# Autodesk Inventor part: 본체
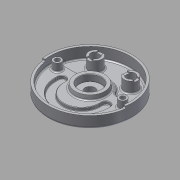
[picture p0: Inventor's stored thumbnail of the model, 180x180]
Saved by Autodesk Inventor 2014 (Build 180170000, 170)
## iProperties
Created: 2015-06
Part Number: 본체
Material: 알루미늄 6061
Document SubType Name: Modeling
Designer: MYHOME
Mass: 1071.05 g
Surface Area: 1034.6 cm^2
Volume: 395.223 cm^3
Density: 2.71 g/cm^3
Appearance: 알루미늄 - 평지
Author: MYHOME
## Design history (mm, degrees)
sketch "스케치1"
  geometry: C1 r 95 at (0, 0); C2 r 90 at (0, 0); 1 further point
  constraints: 2 centre point, 2 coincident
  dimensions: "d0" = 190 diameter of C1; "d1" = 180 diameter of C2
extrude "돌출1" new body sketch "스케치1" distance "d2" = 32; taper "d3" = 0 deg
extrude "돌출2" join sketch "스케치1" distance "d4" = 7; taper "d5" = 0 deg
sketch "스케치3"
  geometry: L1 (-88.566, 16)-(88.566, 16); A1 r 90 centre (0, 0) between (88.566, 16) and (-88.566, 16) reference; A2 r 42 centre (0, 0) between (-38.833, 16) and (38.833, 16)
  constraints: 4 point on circle, 2 end point, 2 point on line, 1 centre point, 1 coincident, 1 horizontal
  dimensions: "d11" = 16 distance from line of A1.centre L1; "d12" = 84 diameter of A2
extrude "돌출4" join sketch "스케치3" distance "d13" = 7; taper "d14" = 0 deg
fillet "모깎기2" dims "d15" = 10
sketch "스케치4"
  geometry: C1 r 15 at (-40, 52); C2 r 15 at (40, 52); A1 r 90 centre (0, 0) between (85.114, 29.25) and (-85.114, 29.25) reference
  constraints: 2 centre point, 1 horizontal alignment
  dimensions: "d16" = 30 diameter of C1; "d17" = 30 diameter of C2; "d18" = 52 vertical distance of A1.centre C2.centre; "d19" = 40 horizontal distance of A1.centre C1.centre; "d20" = 80 distance of C2.centre C1.centre
extrude "돌출5" join sketch "스케치4" distance "d21" = 25; taper "d22" = 0 deg
sketch "스케치5"
  geometry: C1 r 15 at (0, 0) reference; C2 r 15 at (80, 0) reference; C3 r 10 at (0, 0); C4 r 10 at (80, 0); 1 further point
  constraints: 2 centre point, 2 coincident
  dimensions: "d23" = 20 diameter of C3; "d24" = 20 diameter of C4
extrude "돌출6" cut sketch "스케치5" stored distance "d25" = 25; taper "d26" = 0 deg
sketch "스케치6"
  geometry: L1 (-6, 15)-(6, 15); L2 (6, 15)-(6, -15); L3 (6, -15)-(-6, -15); L4 (-6, -15)-(-6, 15); L5 (65, 6)-(95, 6); L6 (95, 6)-(95, -6); L7 (95, -6)-(65, -6); L8 (65, -6)-(65, 6); C1 r 10 at (0, 0) reference; C2 r 15 at (0, 0) reference; C3 r 10 at (80, 0) reference; C4 r 15 at (80, 0) reference; C5 r 15 at (80, 0) reference; 3 further points
  constraints: 16 end point, 4 parallel, 4 tangent, 2 horizontal, 2 midpoint, 2 perpendicular, 1 horizontal alignment, 1 vertical alignment
  dimensions: "d27" = 12 distance of L2.end L3.end; "d28" = 12 distance of L5.end L6.end
extrude "돌출7" cut sketch "스케치6" distance "d29" = 3; taper "d30" = 0 deg
sketch "스케치7"
  geometry: L1 (75.657, 16)-(45.033, 16) reference; L2 (41, -19)-(59, -19); L3 (-41, -19)-(-59, -19); L4 (-41, -14)-(-59, -14); L5 (41, -14)-(59, -14); L6 (-41, -19)-(-41, -14); L7 (-59, -19)-(-59, -14); L8 (41, -19)-(41, -14); L9 (59, -19)-(59, -14); A1 r 42 centre (0, 0) between (36.373, 21) and (-36.373, 21) reference; A2 r 50 centre (0, -19) between (-50, -19) and (50, -19); A3 r 59 centre (0, -19) between (-59, -19) and (59, -19); A4 r 41 centre (0, -19) between (-41, -19) and (41, -19); A5 r 9 centre (-50, -19) between (-41, -19) and (-59, -19); A6 r 9 centre (50, -19) between (59, -19) and (41, -19); A7 r 9 centre (-50, -14) between (-41, -14) and (-59, -14); A8 r 9 centre (50, -14) between (59, -14) and (41, -14)
  constraints: 16 end point, 14 point on circle, 9 tangent, 7 centre point, 3 parallel, 2 midpoint, 1 collinear, 1 perpendicular, 1 vertical alignment
  dimensions: "d33" = 19 distance of A1.centre A2.centre; "d34" = 41 radius of A4; "d35" = 59 radius of A3; "d36" = 5 distance between parallel lines of L3 L4; "d37" = 5 distance between parallel lines of L2 L5
extrude "돌출8" cut sketch "스케치7" distance "d38" = 7; taper "d39" = 0 deg
chamfer "모따기1" distance "d40" = 1; stored, may be unused: second distance "d41" = 2, angle "d42" = 45 deg
fillet "모깎기3" dims "d43" = 1
sketch "스케치8"
  geometry: C1 r 35 at (0, 0); A1 r 90 centre (0, 0) between (-85.114, 29.25) and (85.114, 29.25) reference
  constraints: 1 centre point, 1 coincident
  dimensions: "d44" = 70 diameter of C1
extrude "돌출9" join sketch "스케치8" distance "d45" = 10; taper "d46" = -10 deg
fillet "모깎기4" dims "d47" = 3
sketch "스케치9"
  geometry: C1 r 33.237 at (0, 0) reference; 1 further point
  constraints: 1 coincident
hole "구멍1" sketch "스케치9" at (0, 0) diameter "d48" = 23; stored, may be unused: countersink angle "d52" = 90 deg, drill point angle "d54" = 0 deg; dims "d49" = 6, "d50" = 50, "d51" = 15, "d53" = 8
fillet "모깎기5" dims "d58" = 0.3
sketch "스케치10"
  geometry: C1 r 9 at (-74, 0); C2 r 9 at (74, 0); A1 r 42 centre (0, 0) between (36.373, 21) and (-36.373, 21) reference
  constraints: 2 centre point, 2 horizontal alignment
  dimensions: "d59" = 18 diameter of C1; "d60" = 18 diameter of C2; "d61" = 74 distance of C1.centre A1.centre; "d62" = 148 distance of C2.centre C1.centre
extrude "돌출10" join sketch "스케치10" stored distance "d63" = 10; taper "d64" = 0 deg
fillet "모깎기6" dims "d65" = 3
sketch "스케치11"
  geometry: C1 r 9 at (74, 0) reference; C2 r 9 at (-74, 0) reference; 2 further points
  constraints: 2 coincident
hole "구멍2" sketch "스케치11" at (-74, 0), (74, 0) diameter "d66" = 11; stored, may be unused: countersink angle "d70" = 90 deg, drill point angle "d72" = 0 deg; dims "d67" = 6, "d68" = 18, "d69" = 11, "d71" = 8
sketch "스케치12"
  geometry: L1 (-94.075, -13.221)-(0, 0); L2 (0, 0)-(94.075, -13.221); L3 (0, 0)-(90, 0); L4 (0, 0)-(-90, 0); A1 r 90 centre (0, 0) between (90, 0) and (-90, 0) reference; A2 r 95 centre (0, 0) between (94.075, -13.221) and (-94.075, -13.221) reference; 2 further points
  constraints: 8 end point, 6 point on circle, 2 point on line, 1 collinear, 1 horizontal
  dimensions: "d73" = 8 deg angle of L3 L2; "d74" = 8 deg angle of L4 L1
extrude "돌출11" cut sketch "스케치12" distance "d75" = 5; taper "d76" = 0 deg
fillet "모깎기7" dims "d77" = 3
fillet "모깎기8" dims "d78" = 3
fillet "모깎기9" dims "d79" = 5
fillet "모깎기10" dims "d80" = 3
sketch "스케치13"
  geometry: C1 r 90 at (0, 0) reference; A1 r 68 centre (0, 0) between (0, -68) and (68, 0)
  constraints: 2 point on circle, 1 centre point, 1 coincident, 1 other
  dimensions: "d81" = 68 radius of A1
feature "엠보싱1" sketch "스케치13" dims "d0" = 190, "d1" = 180, "d82" = 0.5, "d83" = 0
fillet "모깎기11" dims "d84" = 3
chamfer "모따기3" distance "d91" = 1; stored, may be unused: second distance "d92" = 2, angle "d93" = 45 deg
sketch "스케치16"
  geometry: C1 r 11.5 at (0, 0) reference; C2 r 26 at (0, 0)
  constraints: 1 centre point, 1 coincident
  dimensions: "d94" = 52 diameter of C2
extrude "돌출14" join sketch "스케치16" distance "d95" = 12; taper "d96" = -15 deg
sketch "스케치17"
  geometry: C1 r 22.785 at (0, 0) reference; C2 r 11.5 at (0, 0)
  constraints: 1 centre point, 1 coincident
  dimensions: "d97" = 23 diameter of C2
extrude "돌출15" cut sketch "스케치17" stored distance "d98" = 12; taper "d99" = 0 deg
fillet "모깎기12" dims "d100" = 1
fillet "모깎기13" dims "d101" = 3
node "솔리드1"
node "투영된 루프1"
